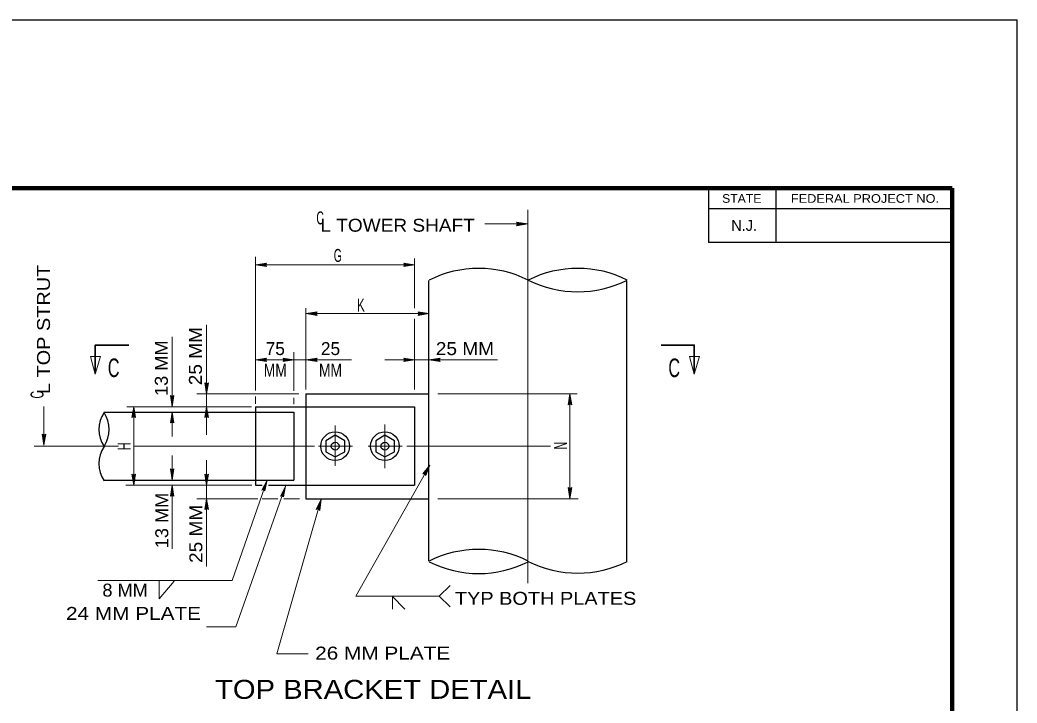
# Model space of a CAD drawing. Extents: x 312601.858 to 312602.699, y 144420.109 to 144420.704.
# Drawn here: x 312602.4677 to 312602.6988, y 144420.5451 to 144420.7035 of the extents above; entities that cross this region are included whole.
import ezdxf
from ezdxf.enums import TextEntityAlignment as Align

# ---------------------------------------------------------------- set-up
doc = ezdxf.new("R2010")
doc.units = 0
doc.header["$LTSCALE"] = 0.0012
doc.linetypes.add('DOT_DASHED', pattern=[7.7, 5, -1.2, 0.3, -1.2])
doc.linetypes.add('MEDIUM_DASHED', pattern=[4.5, 3, -1.5])
for name, color, linetype, lineweight in [('1', 7, 'Continuous', 25), ('2', 7, 'Continuous', 13), ('39', 7, 'Continuous', 13), ('61', 7, 'Continuous', 25), ('9', 7, 'Continuous', 13)]:
    doc.layers.add(name, color=color, linetype=linetype, lineweight=lineweight)

msp = doc.modelspace()

# ---------------------------------------------------------------- hatches: boundary and pattern name
at = {"layer": '39'}
for points in [[(312602.5831, 144420.6562), (312602.5828, 144420.6566), (312602.5854, 144420.6562), (312602.5828, 144420.6558)], [(312602.5246, 144420.6467), (312602.5249, 144420.6463), (312602.5223, 144420.6467), (312602.5249, 144420.6471)], [(312602.5569, 144420.6467), (312602.5567, 144420.6471), (312602.5592, 144420.6467), (312602.5567, 144420.6463)], [(312602.5363, 144420.6354), (312602.5366, 144420.635), (312602.534, 144420.6354), (312602.5366, 144420.6358)], [(312602.5363, 144420.6354), (312602.5366, 144420.635), (312602.534, 144420.6354), (312602.5366, 144420.6358)], [(312602.5602, 144420.6354), (312602.56, 144420.6358), (312602.5625, 144420.6354), (312602.56, 144420.635)], [(312602.5246, 144420.6247), (312602.5249, 144420.6243), (312602.5223, 144420.6247), (312602.5249, 144420.6251)], [(312602.5246, 144420.6247), (312602.5249, 144420.6243), (312602.5223, 144420.6247), (312602.5249, 144420.6251)], [(312602.5289, 144420.6247), (312602.5287, 144420.6251), (312602.5312, 144420.6247), (312602.5287, 144420.6243)], [(312602.5289, 144420.6247), (312602.5287, 144420.6251), (312602.5312, 144420.6247), (312602.5287, 144420.6243)], [(312602.5363, 144420.6247), (312602.5366, 144420.6243), (312602.534, 144420.6247), (312602.5366, 144420.6251)], [(312602.5569, 144420.6247), (312602.5567, 144420.6251), (312602.5592, 144420.6247), (312602.5567, 144420.6243)], [(312602.5569, 144420.6247), (312602.5567, 144420.6251), (312602.5592, 144420.6247), (312602.5567, 144420.6243)], [(312602.5648, 144420.6247), (312602.5651, 144420.6243), (312602.5625, 144420.6247), (312602.5651, 144420.6251)], [(312602.5648, 144420.6247), (312602.5651, 144420.6243), (312602.5625, 144420.6247), (312602.5651, 144420.6251)], [(312602.511, 144420.6191), (312602.5114, 144420.6194), (312602.511, 144420.6168), (312602.5106, 144420.6194)], [(312602.503, 144420.6161), (312602.5034, 144420.6164), (312602.503, 144420.6138), (312602.5026, 144420.6164)], [(312602.5952, 144420.6145), (312602.5948, 144420.6143), (312602.5952, 144420.6168), (312602.5956, 144420.6143)], [(312602.4941, 144420.6115), (312602.4937, 144420.6113), (312602.4941, 144420.6138), (312602.4945, 144420.6113)], [(312602.503, 144420.6103), (312602.5026, 144420.6101), (312602.503, 144420.6126), (312602.5034, 144420.6101)], [(312602.511, 144420.6115), (312602.5106, 144420.6113), (312602.511, 144420.6138), (312602.5114, 144420.6113)], [(312602.4733, 144420.6072), (312602.4737, 144420.6075), (312602.4733, 144420.6049), (312602.4729, 144420.6075)], [(312602.4733, 144420.6072), (312602.4737, 144420.6075), (312602.4733, 144420.6049), (312602.4729, 144420.6075)], [(312602.5616, 144420.5983), (312602.5611, 144420.5983), (312602.5627, 144420.6003), (312602.5618, 144420.5979)], [(312602.4941, 144420.5979), (312602.4945, 144420.5982), (312602.4941, 144420.5956), (312602.4937, 144420.5982)], [(312602.503, 144420.5991), (312602.5034, 144420.5994), (312602.503, 144420.5968), (312602.5026, 144420.5994)], [(312602.511, 144420.5979), (312602.5114, 144420.5982), (312602.511, 144420.5956), (312602.5106, 144420.5982)], [(312602.503, 144420.5933), (312602.5026, 144420.5931), (312602.503, 144420.5956), (312602.5034, 144420.5931)], [(312602.5242, 144420.5946), (312602.5238, 144420.5945), (312602.525, 144420.5968), (312602.5245, 144420.5943)], [(312602.5285, 144420.5932), (312602.5281, 144420.5931), (312602.5293, 144420.5954), (312602.5288, 144420.5929)], [(312602.5952, 144420.5948), (312602.5956, 144420.5951), (312602.5952, 144420.5925), (312602.5948, 144420.5951)], [(312602.511, 144420.5902), (312602.5106, 144420.59), (312602.511, 144420.5925), (312602.5114, 144420.59)], [(312602.5369, 144420.5902), (312602.5364, 144420.59), (312602.5375, 144420.5924), (312602.5372, 144420.5898)]]:
    msp.add_hatch(color=256, dxfattribs=at).paths.add_polyline_path(points)

# ---------------------------------------------------------------- linework, layer by layer
at = {"layer": '1', "lineweight": 13}
for p, q in [((312602.5854, 144420.6595), (312602.5854, 144420.6489)), ((312602.5854, 144420.6562), (312602.5755, 144420.6562)), ((312602.5223, 144420.6486), (312602.5223, 144420.6176)), ((312602.5592, 144420.6467), (312602.5223, 144420.6467)), ((312602.5592, 144420.6482), (312602.5592, 144420.6367)), ((312602.534, 144420.6367), (312602.534, 144420.6178)), ((312602.5625, 144420.6354), (312602.534, 144420.6354)), ((312602.5592, 144420.6342), (312602.5592, 144420.6178)), ((312602.503, 144420.63), (312602.503, 144420.6138)), ((312602.5312, 144420.6265), (312602.5312, 144420.6175)), ((312602.5625, 144420.6247), (312602.5784, 144420.6247)), ((312602.5087, 144420.6168), (312602.5324, 144420.6168)), ((312602.5646, 144420.6168), (312602.5969, 144420.6168)), ((312602.5223, 144420.6162), (312602.5223, 144420.6145)), ((312602.5312, 144420.6159), (312602.5312, 144420.6144)), ((312602.4733, 144420.6139), (312602.4733, 144420.6049)), ((312602.4925, 144420.6138), (312602.5214, 144420.6138)), ((312602.4941, 144420.6138), (312602.4941, 144420.5956)), ((312602.503, 144420.6126), (312602.503, 144420.6069)), ((312602.511, 144420.6138), (312602.511, 144420.6073)), ((312602.471, 144420.6047), (312602.483, 144420.6047)), ((312602.503, 144420.6025), (312602.503, 144420.5968)), ((312602.511, 144420.6014), (312602.511, 144420.5956)), ((312602.4923, 144420.5956), (312602.5215, 144420.5956)), ((312602.503, 144420.5956), (312602.503, 144420.5809)), ((312602.511, 144420.5956), (312602.511, 144420.5925)), ((312602.525, 144420.5968), (312602.5169, 144420.5735)), ((312602.5087, 144420.5925), (312602.5229, 144420.5925)), ((312602.511, 144420.5925), (312602.511, 144420.5768)), ((312602.5239, 144420.5925), (312602.5275, 144420.5925)), ((312602.5289, 144420.5925), (312602.5325, 144420.5925)), ((312602.5646, 144420.5925), (312602.5971, 144420.5925)), ((312602.4858, 144420.5735), (312602.5169, 144420.5735)), ((312602.5569, 144420.5669), (312602.554, 144420.5699)), ((312602.5541, 144420.5699), (312602.5541, 144420.5669))]:
    msp.add_line(p, q, dxfattribs=at)
at = {"layer": '1', "linetype": 'DOT_DASHED', "lineweight": 13}
for p, q in [((312602.5854, 144420.6565), (312602.5854, 144420.5729)), ((312602.5408, 144420.6095), (312602.5408, 144420.6001)), ((312602.5523, 144420.6097), (312602.5523, 144420.5998)), ((312602.5523, 144420.6095), (312602.5523, 144420.5996)), ((312602.4733, 144420.6047), (312602.4906, 144420.6047)), ((312602.4941, 144420.6047), (312602.536, 144420.6047)), ((312602.5369, 144420.6047), (312602.5448, 144420.6047)), ((312602.5484, 144420.6047), (312602.5563, 144420.6047)), ((312602.5574, 144420.6047), (312602.5907, 144420.6047))]:
    msp.add_line(p, q, dxfattribs=at)
at = {"layer": '1'}
for p, q in [((312602.5625, 144420.578), (312602.5625, 144420.6431)), ((312602.6084, 144420.5779), (312602.6084, 144420.6431)), ((312602.534, 144420.6168), (312602.534, 144420.5925)), ((312602.534, 144420.6168), (312602.5625, 144420.6168)), ((312602.4872, 144420.6126), (312602.5312, 144420.6126)), ((312602.5223, 144420.6138), (312602.5223, 144420.6126)), ((312602.5223, 144420.6138), (312602.534, 144420.6138)), ((312602.5312, 144420.6126), (312602.5312, 144420.5968)), ((312602.4872, 144420.5968), (312602.5312, 144420.5968)), ((312602.5223, 144420.5968), (312602.5223, 144420.5956)), ((312602.5223, 144420.5956), (312602.5239, 144420.5956)), ((312602.5253, 144420.5956), (312602.534, 144420.5956)), ((312602.534, 144420.5925), (312602.5625, 144420.5925))]:
    msp.add_line(p, q, dxfattribs=at)
at = {"layer": '1', "linetype": 'MEDIUM_DASHED'}
for p, q in [((312602.5223, 144420.6126), (312602.5223, 144420.5968)), ((312602.534, 144420.6138), (312602.5592, 144420.6138)), ((312602.5592, 144420.6138), (312602.5592, 144420.5956)), ((312602.534, 144420.5956), (312602.5592, 144420.5956))]:
    msp.add_line(p, q, dxfattribs=at)
at = {"layer": '1', "lineweight": 13}
for points in [[(312602.511, 144420.6328), (312602.511, 144420.6168), (312602.511, 144420.6138)], [(312602.5223, 144420.6247), (312602.5312, 144420.6247), (312602.534, 144420.6247), (312602.5446, 144420.6247)], [(312602.5523, 144420.6247), (312602.5592, 144420.6247), (312602.5625, 144420.6247)], [(312602.511, 144420.5628), (312602.5178, 144420.5628), (312602.5293, 144420.5954)], [(312602.5345, 144420.5565), (312602.5273, 144420.5565), (312602.5375, 144420.5924)], [(312602.5, 144420.5734), (312602.5, 144420.5693), (312602.5035, 144420.5734)]]:
    msp.add_lwpolyline(points, dxfattribs=at)
at = {"layer": '1', "lineweight": 35}
for points in [[(312602.4852, 144420.6218), (312602.4852, 144420.6281), (312602.493, 144420.6281)], [(312602.624, 144420.6218), (312602.624, 144420.6281), (312602.6163, 144420.6281)]]:
    msp.add_lwpolyline(points, dxfattribs=at)
at = {"layer": '1'}
for points in [[(312602.5408, 144420.6022), (312602.543, 144420.6034), (312602.543, 144420.6059), (312602.5408, 144420.6072), (312602.5386, 144420.6059), (312602.5386, 144420.6034)], [(312602.5523, 144420.6022), (312602.5545, 144420.6034), (312602.5545, 144420.6059), (312602.5523, 144420.6072), (312602.5502, 144420.6059), (312602.5502, 144420.6034)]]:
    msp.add_lwpolyline(points, close=True, dxfattribs=at)
for centre, radius in [((312602.54079, 144420.60468), 0.00333), ((312602.55231, 144420.60468), 0.00333), ((312602.54079, 144420.60468), 0.0009), ((312602.55231, 144420.60468), 0.0009)]:
    msp.add_circle(centre, radius, dxfattribs=at)
at = {"layer": '2'}
msp.add_line((312602.5952, 144420.6168), (312602.5952, 144420.5925), dxfattribs=at)
for points in [[(312602.5627, 144420.6003), (312602.5456, 144420.5699), (312602.5649, 144420.5699)], [(312602.5674, 144420.5674), (312602.5649, 144420.5699), (312602.5674, 144420.5724)]]:
    msp.add_lwpolyline(points, dxfattribs=at)
at = {"layer": '2', "lineweight": 25}
for centre, radius, start, end in [((312602.574045, 144420.620281), 0.025613, 63.38393, 116.61607), ((312602.596995, 144420.620281), 0.025613, 63.38393, 116.61607), ((312602.596995, 144420.666079), 0.025613, 243.38393, 296.61607), ((312602.493323, 144420.60855), 0.007275, 147.02071, 212.97929), ((312602.481117, 144420.60855), 0.007275, 327.02071, 32.97929), ((312602.493323, 144420.60063), 0.007275, 147.02071, 212.97929), ((312602.574045, 144420.555141), 0.025613, 63.38393, 116.61607), ((312602.574045, 144420.600759), 0.025613, 243.38393, 296.61607), ((312602.596995, 144420.600849), 0.025613, 243.38393, 296.61607)]:
    msp.add_arc(centre, radius, start, end, dxfattribs=at)
at = {"layer": '39', "lineweight": 25}
for p, q in [((312601.8578, 144420.7035), (312602.6988, 144420.7035)), ((312602.6988, 144420.1095), (312602.6988, 144420.7035)), ((312602.5735, 144420.6645), (312602.6838, 144420.6645)), ((312602.6838, 144420.6514), (312602.6838, 144420.6645))]:
    msp.add_line(p, q, dxfattribs=at)
at = {"layer": '39', "lineweight": 158}
for p in [(312601.9088, 144420.6645), (312602.6838, 144420.1247)]:
    msp.add_line(p, (312602.6838, 144420.6645), dxfattribs=at)
at = {"layer": '39'}
for points in [[(312602.5831, 144420.6562), (312602.5828, 144420.6566), (312602.5854, 144420.6562), (312602.5828, 144420.6558)], [(312602.5246, 144420.6467), (312602.5249, 144420.6463), (312602.5223, 144420.6467), (312602.5249, 144420.6471)], [(312602.5569, 144420.6467), (312602.5567, 144420.6471), (312602.5592, 144420.6467), (312602.5567, 144420.6463)], [(312602.5363, 144420.6354), (312602.5366, 144420.635), (312602.534, 144420.6354), (312602.5366, 144420.6358)], [(312602.5363, 144420.6354), (312602.5366, 144420.635), (312602.534, 144420.6354), (312602.5366, 144420.6358)], [(312602.5602, 144420.6354), (312602.56, 144420.6358), (312602.5625, 144420.6354), (312602.56, 144420.635)], [(312602.5246, 144420.6247), (312602.5249, 144420.6243), (312602.5223, 144420.6247), (312602.5249, 144420.6251)], [(312602.5246, 144420.6247), (312602.5249, 144420.6243), (312602.5223, 144420.6247), (312602.5249, 144420.6251)], [(312602.5289, 144420.6247), (312602.5287, 144420.6251), (312602.5312, 144420.6247), (312602.5287, 144420.6243)], [(312602.5289, 144420.6247), (312602.5287, 144420.6251), (312602.5312, 144420.6247), (312602.5287, 144420.6243)], [(312602.5363, 144420.6247), (312602.5366, 144420.6243), (312602.534, 144420.6247), (312602.5366, 144420.6251)], [(312602.5569, 144420.6247), (312602.5567, 144420.6251), (312602.5592, 144420.6247), (312602.5567, 144420.6243)], [(312602.5569, 144420.6247), (312602.5567, 144420.6251), (312602.5592, 144420.6247), (312602.5567, 144420.6243)], [(312602.5648, 144420.6247), (312602.5651, 144420.6243), (312602.5625, 144420.6247), (312602.5651, 144420.6251)], [(312602.5648, 144420.6247), (312602.5651, 144420.6243), (312602.5625, 144420.6247), (312602.5651, 144420.6251)], [(312602.511, 144420.6191), (312602.5114, 144420.6194), (312602.511, 144420.6168), (312602.5106, 144420.6194)], [(312602.503, 144420.6161), (312602.5034, 144420.6164), (312602.503, 144420.6138), (312602.5026, 144420.6164)], [(312602.5952, 144420.6145), (312602.5948, 144420.6143), (312602.5952, 144420.6168), (312602.5956, 144420.6143)], [(312602.4941, 144420.6115), (312602.4937, 144420.6113), (312602.4941, 144420.6138), (312602.4945, 144420.6113)], [(312602.503, 144420.6103), (312602.5026, 144420.6101), (312602.503, 144420.6126), (312602.5034, 144420.6101)], [(312602.511, 144420.6115), (312602.5106, 144420.6113), (312602.511, 144420.6138), (312602.5114, 144420.6113)], [(312602.4733, 144420.6072), (312602.4737, 144420.6075), (312602.4733, 144420.6049), (312602.4729, 144420.6075)], [(312602.4733, 144420.6072), (312602.4737, 144420.6075), (312602.4733, 144420.6049), (312602.4729, 144420.6075)], [(312602.5616, 144420.5983), (312602.5611, 144420.5983), (312602.5627, 144420.6003), (312602.5618, 144420.5979)], [(312602.4941, 144420.5979), (312602.4945, 144420.5982), (312602.4941, 144420.5956), (312602.4937, 144420.5982)], [(312602.503, 144420.5991), (312602.5034, 144420.5994), (312602.503, 144420.5968), (312602.5026, 144420.5994)], [(312602.511, 144420.5979), (312602.5114, 144420.5982), (312602.511, 144420.5956), (312602.5106, 144420.5982)], [(312602.503, 144420.5933), (312602.5026, 144420.5931), (312602.503, 144420.5956), (312602.5034, 144420.5931)], [(312602.5242, 144420.5946), (312602.5238, 144420.5945), (312602.525, 144420.5968), (312602.5245, 144420.5943)], [(312602.5285, 144420.5932), (312602.5281, 144420.5931), (312602.5293, 144420.5954), (312602.5288, 144420.5929)], [(312602.5952, 144420.5948), (312602.5956, 144420.5951), (312602.5952, 144420.5925), (312602.5948, 144420.5951)], [(312602.511, 144420.5902), (312602.5106, 144420.59), (312602.511, 144420.5925), (312602.5114, 144420.59)], [(312602.5369, 144420.5902), (312602.5364, 144420.59), (312602.5375, 144420.5924), (312602.5372, 144420.5898)]]:
    msp.add_lwpolyline(points, close=True, dxfattribs=at)
at = {"layer": '61'}
for p, q in [((312602.6273, 144420.6645), (312602.6273, 144420.6519)), ((312602.6429, 144420.6645), (312602.6429, 144420.6519)), ((312602.6838, 144420.6597), (312602.6273, 144420.6597)), ((312602.6838, 144420.6519), (312602.6273, 144420.6519))]:
    msp.add_line(p, q, dxfattribs=at)
at = {"layer": '9'}
for points in [[(312602.4852, 144420.6214), (312602.4864, 144420.6255), (312602.4841, 144420.6255)], [(312602.6229, 144420.6255), (312602.624, 144420.6214), (312602.6252, 144420.6255)]]:
    msp.add_lwpolyline(points, close=True, dxfattribs=at)

# ---------------------------------------------------------------- texts
at = {"layer": '2'}
for s, height, width, p in [('C', 0.003, 0.6, (312602.5373, 144420.6561)), ('L TOWER SHAFT', 0.003, 1.1, (312602.55525, 144420.6544)), ('G', 0.003, 0.6, (312602.5414, 144420.6474)), ('K', 0.003, 0.65, (312602.54675, 144420.6359)), ('25 MM', 0.003, 1.1, (312602.57085, 144420.6258)), ('C', 0.0043, 0.65, (312602.48945, 144420.6207)), ('MM', 0.003, 0.8, (312602.5269, 144420.6208)), ('MM', 0.003, 0.8, (312602.5397, 144420.6208)), ('C', 0.0043, 0.65, (312602.61935, 144420.6207)), ('8 MM', 0.003, 1.05, (312602.4921, 144420.5698)), ('TYP BOTH PLATES', 0.003, 1.15, (312602.58955, 144420.5679)), ('24 MM PLATE', 0.003, 1.2, (312602.49405, 144420.5644)), ('26 MM PLATE', 0.003, 1.2, (312602.5518, 144420.5552)), ('TOP BRACKET DETAIL', 0.0044, 1.15, (312602.5496, 144420.5461))]:
    msp.add_text(s, height=height, dxfattribs=dict(at, width=width)).set_placement(p, align=Align.CENTER)
for s, width, p in [('L TOP STRUT', 1.15, (312602.4747, 144420.63175)), ('25 MM', 1.1, (312602.5099, 144420.62555)), ('13 MM', 1.05, (312602.502, 144420.62275)), ('C', 0.6, (312602.4732, 144420.6166)), ('H', 0.6, (312602.4934, 144420.60465)), ('N', 0.6, (312602.5945, 144420.6048)), ('13 MM', 1.05, (312602.5021, 144420.58745)), ('25 MM', 1.1, (312602.51, 144420.58435))]:
    msp.add_text(s, height=0.003, rotation=90, dxfattribs=dict(at, width=width)).set_placement(p, align=Align.CENTER)
for s, p in [('75', (312602.5269, 144420.6258)), ('25', (312602.5397, 144420.6258))]:
    msp.add_text(s, height=0.003, dxfattribs=at).set_placement(p, align=Align.CENTER)
at = {"layer": '61'}
for s, width, p in [('STATE', 1.05, (312602.635, 144420.6611)), ('FEDERAL PROJECT NO.', 1.1, (312602.66355, 144420.6611))]:
    msp.add_text(s, height=0.00201, dxfattribs=dict(at, width=width)).set_placement(p, align=Align.CENTER)
msp.add_text('N.J.', height=0.002512, dxfattribs=at).set_placement((312602.63555, 144420.6546), align=Align.CENTER)

doc.saveas('drawing.dxf')
